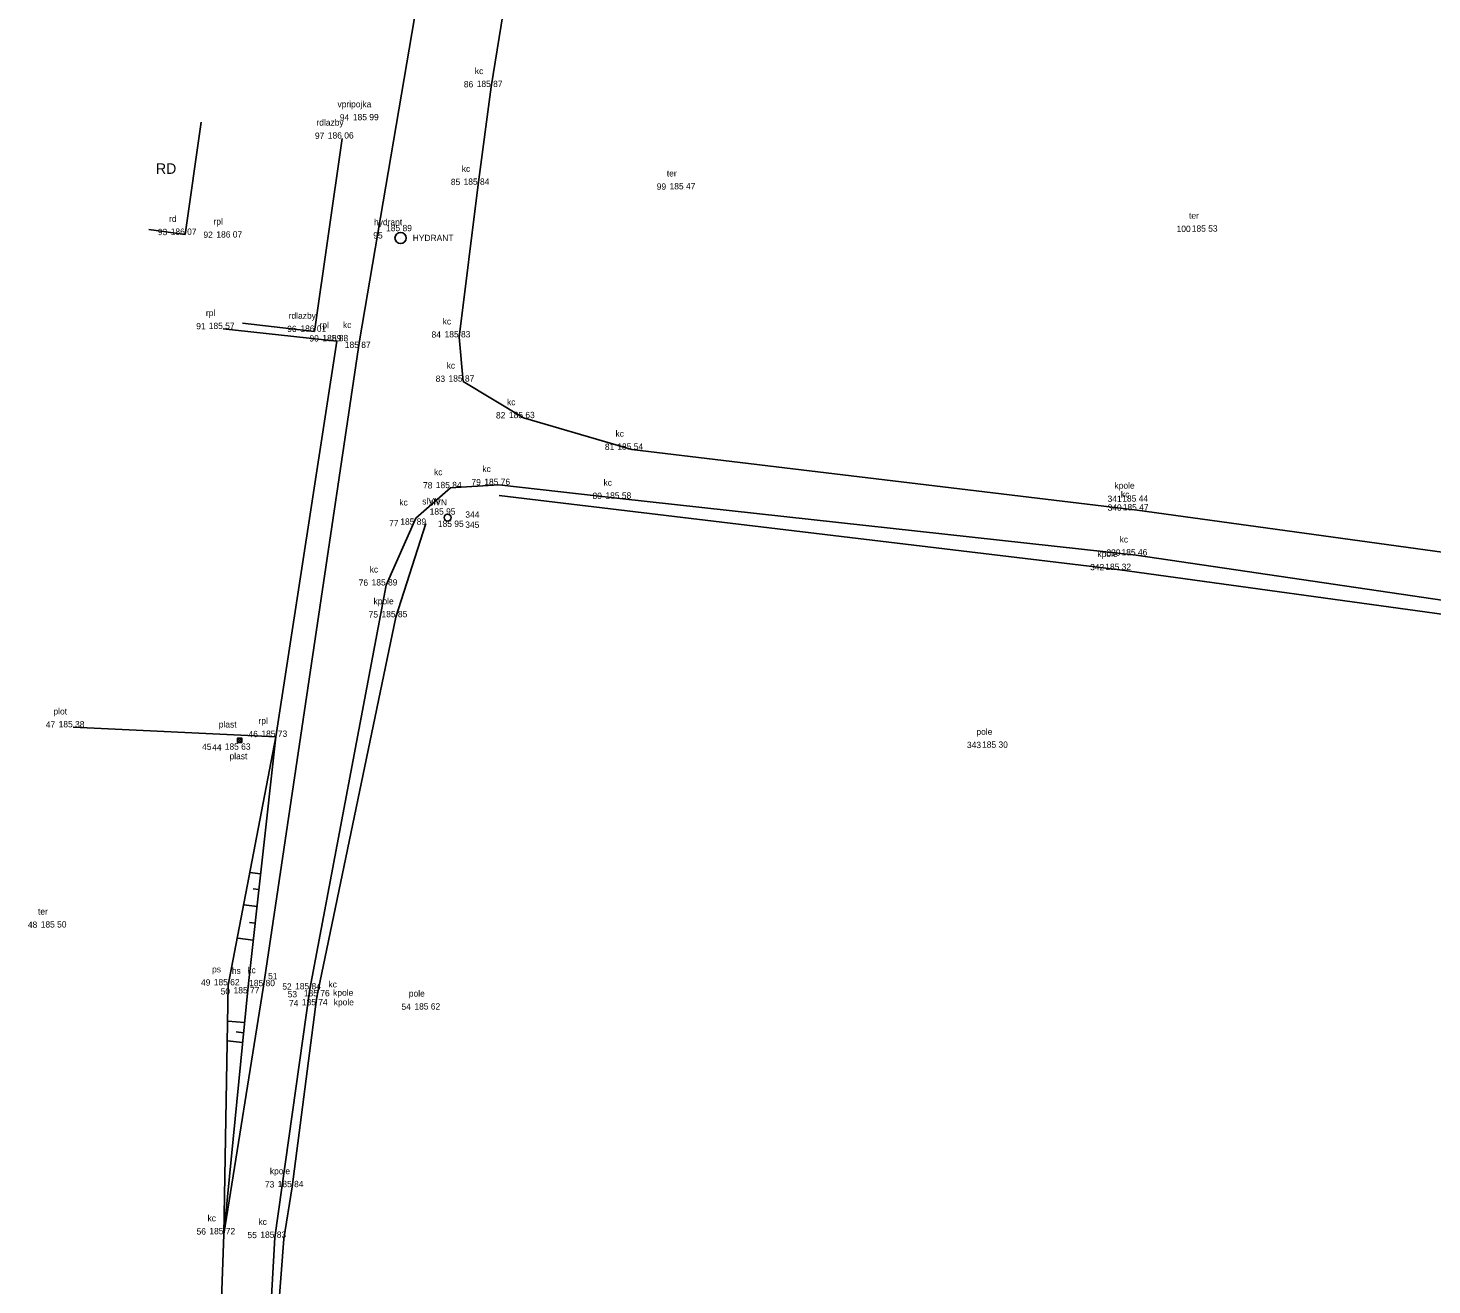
# Model space of a CAD drawing. Extents: x -598527 to -598215, y -1172822 to -1172560.
# Drawn here: x -598521.3 to -598454.5, y -1172719.8 to -1172660 of the extents above; entities that cross this region are included whole.
import ezdxf

# ---------------------------------------------------------------- set-up
doc = ezdxf.new("R2010")
doc.units = 0
for name, color, linetype in [('Body', 7, 'Continuous'), ('Body čísla', 7, 'Continuous'), ('Kody', 7, 'Continuous'), ('Kraj pole', 7, 'Continuous'), ('PATTERN_CLASS', 7, 'Continuous'), ('Ploty', 7, 'Continuous'), ('Popisy objektu', 7, 'Continuous'), ('Sachty', 7, 'Continuous'), ('Výšky', 7, 'Continuous')]:
    doc.layers.add(name, color=color, linetype=linetype)

msp = doc.modelspace()

# ---------------------------------------------------------------- linework, layer by layer
at = {"layer": 'Body'}
for p, q in [((-598499.27, -1172662.77), (-598499.27, -1172662.77)), ((-598505.16, -1172664.35), (-598505.16, -1172664.35)), ((-598506.35, -1172665.22), (-598506.35, -1172665.22)), ((-598499.89, -1172667.42), (-598499.89, -1172667.42)), ((-598490.1, -1172667.64), (-598490.1, -1172667.64)), ((-598513.82, -1172669.8), (-598513.82, -1172669.8)), ((-598511.65, -1172669.93), (-598511.65, -1172669.93)), ((-598503.58, -1172669.96), (-598503.58, -1172669.96)), ((-598465.27, -1172669.65), (-598465.27, -1172669.65)), ((-598512.01, -1172674.28), (-598512.01, -1172674.28)), ((-598507.67, -1172674.41), (-598507.67, -1172674.41)), ((-598506.61, -1172674.86), (-598506.61, -1172674.86)), ((-598505.54, -1172674.85), (-598505.54, -1172674.85)), ((-598500.8, -1172674.68), (-598500.8, -1172674.68)), ((-598500.61, -1172676.78), (-598500.61, -1172676.78)), ((-598497.74, -1172678.52), (-598497.74, -1172678.52)), ((-598492.58, -1172680.02), (-598492.58, -1172680.02)), ((-598501.21, -1172681.85), (-598501.21, -1172681.85)), ((-598498.91, -1172681.7), (-598498.91, -1172681.7)), ((-598493.15, -1172682.35), (-598493.15, -1172682.35)), ((-598468.57, -1172682.49), (-598468.57, -1172682.49)), ((-598468.55, -1172682.91), (-598468.55, -1172682.91)), ((-598502.86, -1172683.29), (-598502.86, -1172683.29)), ((-598501.51, -1172683.24), (-598501.51, -1172683.24)), ((-598501.18, -1172683.29), (-598501.18, -1172683.29)), ((-598468.61, -1172685.05), (-598468.61, -1172685.05)), ((-598469.38, -1172685.74), (-598469.38, -1172685.74)), ((-598504.27, -1172686.48), (-598504.27, -1172686.48)), ((-598503.8, -1172687.99), (-598503.8, -1172687.99)), ((-598519.15, -1172693.23), (-598519.15, -1172693.23)), ((-598511.23, -1172693.85), (-598511.23, -1172693.85)), ((-598511.23, -1172693.85), (-598511.23, -1172693.85)), ((-598509.51, -1172693.68), (-598509.51, -1172693.68)), ((-598475.24, -1172694.2), (-598475.24, -1172694.2)), ((-598520, -1172702.75), (-598520, -1172702.75)), ((-598511.77, -1172705.5), (-598511.77, -1172705.5)), ((-598510.83, -1172705.57), (-598510.83, -1172705.57)), ((-598510.09, -1172705.54), (-598510.09, -1172705.54)), ((-598507.9, -1172705.69), (-598507.9, -1172705.69)), ((-598507.58, -1172706.16), (-598507.58, -1172706.16)), ((-598507.49, -1172705.75), (-598507.49, -1172705.75)), ((-598502.23, -1172706.65), (-598502.23, -1172706.65)), ((-598508.73, -1172715.1), (-598508.73, -1172715.1)), ((-598511.98, -1172717.34), (-598511.98, -1172717.34)), ((-598509.56, -1172717.51), (-598509.56, -1172717.51))]:
    msp.add_line(p, q, dxfattribs=at)
at = {"layer": 'Kraj pole'}
for p, q in [((-598469.38, -1172685.74), (-598498.887, -1172682.207)), ((-598503.8, -1172687.99), (-598502.379, -1172683.533)), ((-598507.49, -1172705.75), (-598503.8, -1172687.99)), ((-598508.73, -1172715.1), (-598507.58, -1172706.16))]:
    msp.add_line(p, q, dxfattribs=at)
msp.add_lwpolyline([(-598508.73, -1172715.1), (-598509.129, -1172717.565), (-598509.8, -1172726.3)], dxfattribs=at)
at = {"layer": 'PATTERN_CLASS'}
for p, q in [((-598513.82, -1172669.8), (-598513.059, -1172664.452)), ((-598506.35, -1172665.22), (-598507.67, -1172674.41)), ((-598513.82, -1172669.8), (-598515.549, -1172669.554)), ((-598507.67, -1172674.41), (-598511.097, -1172674.007)), ((-598507.9, -1172705.69), (-598504.27, -1172686.48)), ((-598511.77, -1172705.5), (-598509.51, -1172693.68)), ((-598511.33, -1172693.95), (-598511.13, -1172693.75)), ((-598511.33, -1172693.75), (-598511.13, -1172693.95)), ((-598510.83, -1172705.57), (-598509.51, -1172693.68)), ((-598510.233, -1172700.196), (-598510.747, -1172700.139)), ((-598510.317, -1172700.945), (-598510.587, -1172700.915)), ((-598510.406, -1172701.753), (-598511.037, -1172701.683)), ((-598510.495, -1172702.549), (-598510.765, -1172702.519)), ((-598510.584, -1172703.352), (-598511.321, -1172703.27)), ((-598511.77, -1172705.5), (-598511.98, -1172717.34)), ((-598510.83, -1172705.57), (-598511.98, -1172717.34)), ((-598507.58, -1172706.16), (-598507.49, -1172705.75)), ((-598510.997, -1172707.282), (-598511.786, -1172707.205)), ((-598511.089, -1172708.221), (-598511.813, -1172708.15)), ((-598511.044, -1172707.761), (-598511.396, -1172707.727))]:
    msp.add_line(p, q, dxfattribs=at)
for points in [[(-598493.82, -1172601.11), (-598496.86, -1172617.82), (-598501.92, -1172653.61), (-598505.54, -1172674.85)], [(-598492.58, -1172680.02), (-598497.74, -1172678.52), (-598500.61, -1172676.78), (-598500.8, -1172674.68), (-598499.89, -1172667.42), (-598499.27, -1172662.77), (-598497.93, -1172654.45), (-598492.18, -1172618.41), (-598490.87, -1172609.63), (-598489.84, -1172601.31)], [(-598511.98, -1172717.34), (-598510.09, -1172705.54), (-598505.54, -1172674.85)], [(-598492.58, -1172680.02), (-598468.55, -1172682.91), (-598441.63, -1172686.62), (-598421.91, -1172689.41), (-598395.91, -1172693.05), (-598382.12, -1172695.14), (-598364.75, -1172697.57), (-598348.85, -1172699.43), (-598326.25, -1172702.17), (-598291.63, -1172707.83), (-598276.21, -1172710.42), (-598272.67, -1172710.2), (-598270.07, -1172709.11), (-598268.17, -1172706.75)], [(-598504.27, -1172686.48), (-598502.86, -1172683.29), (-598501.21, -1172681.85), (-598498.91, -1172681.7), (-598493.15, -1172682.35), (-598468.61, -1172685.05), (-598441.9, -1172688.98), (-598422.43, -1172691.66), (-598396.42, -1172695.27), (-598382.3, -1172697.44), (-598365.39, -1172699.67), (-598349.07, -1172701.68), (-598326.56, -1172704.69), (-598292, -1172710.32), (-598276.32, -1172712.66), (-598273.75, -1172712.88), (-598270.71, -1172712.27), (-598268.64, -1172711.13), (-598269.17, -1172714.46)], [(-598472.39, -1172818.45), (-598479.4, -1172804.1), (-598488.6, -1172784.48), (-598499.71, -1172764.97), (-598504.53, -1172755), (-598507.77, -1172746.6), (-598509.84, -1172736.8), (-598510.17, -1172728.48), (-598509.56, -1172717.51), (-598507.9, -1172705.69)], [(-598474.23, -1172819.49), (-598481.46, -1172805), (-598491.03, -1172785.9), (-598501.92, -1172765.58), (-598506.72, -1172756.28), (-598510.41, -1172747.04), (-598512.46, -1172737.25), (-598512.37, -1172728.07), (-598511.98, -1172717.34)]]:
    msp.add_lwpolyline(points, dxfattribs=at)
msp.add_lwpolyline([(-598511.33, -1172693.95), (-598511.13, -1172693.95), (-598511.13, -1172693.75), (-598511.33, -1172693.75)], close=True, dxfattribs=at)
msp.add_circle((-598501.344, -1172683.259), 0.167, dxfattribs=at)
at = {"layer": 'Ploty'}
for p, q in [((-598506.61, -1172674.86), (-598512.01, -1172674.28)), ((-598509.51, -1172693.68), (-598506.61, -1172674.86)), ((-598469.38, -1172685.74), (-598396.57, -1172695.76)), ((-598509.51, -1172693.68), (-598519.15, -1172693.23))]:
    msp.add_line(p, q, dxfattribs=at)
at = {"layer": 'Sachty'}
msp.add_circle((-598503.58, -1172669.96), 0.266, dxfattribs=at)

# ---------------------------------------------------------------- texts
at = {"layer": 'Body čísla'}
for s, p in [('86', (-598500.57, -1172662.793)), ('94', (-598506.467, -1172664.373)), ('97', (-598507.651, -1172665.243)), ('85', (-598501.188, -1172667.443)), ('99', (-598491.399, -1172667.663)), ('93', (-598515.12, -1172669.823)), ('100', (-598466.68, -1172669.673)), ('92', (-598512.953, -1172669.953)), ('95', (-598504.878, -1172669.983)), ('91', (-598513.294, -1172674.303)), ('96', (-598508.97, -1172674.433)), ('90', (-598507.913, -1172674.883)), ('89', (-598506.839, -1172674.873)), ('84', (-598502.107, -1172674.703)), ('83', (-598501.91, -1172676.803)), ('82', (-598499.043, -1172678.543)), ('81', (-598493.864, -1172680.043)), ('78', (-598502.511, -1172681.873)), ('79', (-598500.209, -1172681.723)), ('80', (-598494.453, -1172682.373)), ('341', (-598469.961, -1172682.513)), ('340', (-598469.96, -1172682.933)), ('77', (-598504.126, -1172683.679)), ('345', (-598500.505, -1172683.746)), ('344', (-598500.499, -1172683.263)), ('339', (-598470.016, -1172685.073)), ('342', (-598470.791, -1172685.763)), ('76', (-598505.57, -1172686.503)), ('75', (-598505.098, -1172688.013)), ('47', (-598520.451, -1172693.253)), ('46', (-598510.81, -1172693.703)), ('45', (-598513.015, -1172694.309)), ('44', (-598512.537, -1172694.34)), ('343', (-598476.647, -1172694.223)), ('48', (-598521.301, -1172702.773)), ('51', (-598509.877, -1172705.218)), ('49', (-598513.069, -1172705.523)), ('50', (-598512.133, -1172705.944)), ('52', (-598509.203, -1172705.713)), ('53', (-598508.948, -1172706.079)), ('74', (-598508.887, -1172706.507)), ('54', (-598503.537, -1172706.673)), ('73', (-598510.03, -1172715.123)), ('56', (-598513.28, -1172717.363)), ('55', (-598510.858, -1172717.533))]:
    msp.add_text(s, height=0.3, dxfattribs=at).set_placement(p)
at = {"layer": 'Kody'}
for s, p in [('kc', (-598500.048, -1172662.163)), ('vpripojka', (-598506.578, -1172663.743)), ('rdlazby', (-598507.58, -1172664.613)), ('kc', (-598500.668, -1172666.813)), ('ter', (-598490.919, -1172667.033)), ('rd', (-598514.589, -1172669.193)), ('ter', (-598466.089, -1172669.043)), ('rpl', (-598512.476, -1172669.323)), ('hydrant', (-598504.841, -1172669.353)), ('rpl', (-598512.836, -1172673.673)), ('rdlazby', (-598508.9, -1172673.803)), ('rpl', (-598507.436, -1172674.253)), ('kc', (-598506.318, -1172674.243)), ('kc', (-598501.578, -1172674.073)), ('kc', (-598501.388, -1172676.173)), ('kc', (-598498.518, -1172677.913)), ('kc', (-598493.358, -1172679.413)), ('kc', (-598501.988, -1172681.243)), ('kc', (-598499.688, -1172681.093)), ('kc', (-598493.928, -1172681.743)), ('kpole', (-598469.634, -1172681.883)), ('kc', (-598469.328, -1172682.303)), ('kc', (-598503.638, -1172682.683)), ('slVN', (-598502.549, -1172682.633)), ('slVN', (-598502.219, -1172682.683)), ('kc', (-598469.388, -1172684.443)), ('kpole', (-598470.444, -1172685.133)), ('kc', (-598505.048, -1172685.873)), ('kpole', (-598504.864, -1172687.383)), ('plot', (-598520.085, -1172692.623)), ('plast', (-598512.224, -1172693.243)), ('rpl', (-598510.336, -1172693.073)), ('pole', (-598476.197, -1172693.593)), ('ter', (-598520.819, -1172702.143)), ('ps', (-598512.541, -1172704.893)), ('hs', (-598511.601, -1172704.963)), ('kc', (-598510.868, -1172704.933)), ('kc', (-598507.009, -1172705.608)), ('kpole', (-598506.787, -1172706.006)), ('kpole', (-598506.757, -1172706.461)), ('pole', (-598503.187, -1172706.043)), ('kpole', (-598509.794, -1172714.493)), ('kc', (-598512.758, -1172716.733)), ('kc', (-598510.338, -1172716.903))]:
    msp.add_text(s, height=0.3, dxfattribs=at).set_placement(p)
at = {"layer": 'PATTERN_CLASS'}
msp.add_text('plast', height=0.3, dxfattribs=at).set_placement((-598511.713, -1172694.756))
at = {"layer": 'Popisy objektu'}
msp.add_text('RD', height=0.5, dxfattribs=at).set_placement((-598515.211, -1172666.908))
at = {"layer": 'Výšky'}
for s, p in [('185 87', (-598499.959, -1172662.778)), ('185 99', (-598505.847, -1172664.358)), ('186 06', (-598507.038, -1172665.228)), ('185 84', (-598500.584, -1172667.428)), ('185 47', (-598490.789, -1172667.648)), ('186 07', (-598514.509, -1172669.808)), ('185 89', (-598504.267, -1172669.635)), ('185 53', (-598465.957, -1172669.658)), ('186 07', (-598512.339, -1172669.938)), ('HYDRANT', (-598503.001, -1172670.106)), ('185 57', (-598512.699, -1172674.288)), ('186 01', (-598508.341, -1172674.418)), ('185 88', (-598507.298, -1172674.868)), ('185 87', (-598506.229, -1172675.189)), ('185 83', (-598501.487, -1172674.688)), ('185 87', (-598501.299, -1172676.788)), ('185 63', (-598498.427, -1172678.528)), ('185 54', (-598493.274, -1172680.028)), ('185 84', (-598501.904, -1172681.858)), ('185 76', (-598499.598, -1172681.708)), ('185 58', (-598493.838, -1172682.358)), ('185 44', (-598469.264, -1172682.498)), ('185 95', (-598502.196, -1172683.118)), ('185 47', (-598469.239, -1172682.918)), ('185 89', (-598503.592, -1172683.601)), ('185 95', (-598501.806, -1172683.7)), ('185 46', (-598469.298, -1172685.058)), ('185 32', (-598470.071, -1172685.748)), ('185 89', (-598504.957, -1172686.488)), ('185 85', (-598504.486, -1172687.998)), ('185 38', (-598519.838, -1172693.238)), ('185 73', (-598510.197, -1172693.688)), ('185 63', (-598511.939, -1172694.3)), ('185 30', (-598475.93, -1172694.208)), ('185 50', (-598520.69, -1172702.758)), ('185 62', (-598512.461, -1172705.508)), ('185 77', (-598511.519, -1172705.892)), ('185 80', (-598510.78, -1172705.548)), ('185 84', (-598508.594, -1172705.698)), ('185 74', (-598508.274, -1172706.457)), ('185 76', (-598508.178, -1172706.032)), ('185 62', (-598502.921, -1172706.658)), ('185 84', (-598509.424, -1172715.108)), ('185 72', (-598512.671, -1172717.348)), ('185 83', (-598510.247, -1172717.518))]:
    msp.add_text(s, height=0.3, dxfattribs=at).set_placement(p)

doc.saveas('drawing.dxf')
